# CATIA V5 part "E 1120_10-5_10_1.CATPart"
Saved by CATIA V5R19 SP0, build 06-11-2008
Part number: E 1120_10-5_10_1
Definition: E 1120_10-5_10_1
Nomenclature: E 1120_10-5_10_1
Source: Unknown
Description: PART--DESC
Bounding box of the stored display mesh (mm): x -33 to -17, y -8 to 8, z -45 to -30
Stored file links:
  C:\Users\jsmid\Desktop\DP_Smidak_Forma LEGO\E 1120_10-5_10_1.CATPart
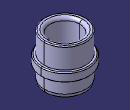
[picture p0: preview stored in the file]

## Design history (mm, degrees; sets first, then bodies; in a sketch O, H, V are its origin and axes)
Body1 "E 1120_10-5_10" (main body)
  Solid1: solid without history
